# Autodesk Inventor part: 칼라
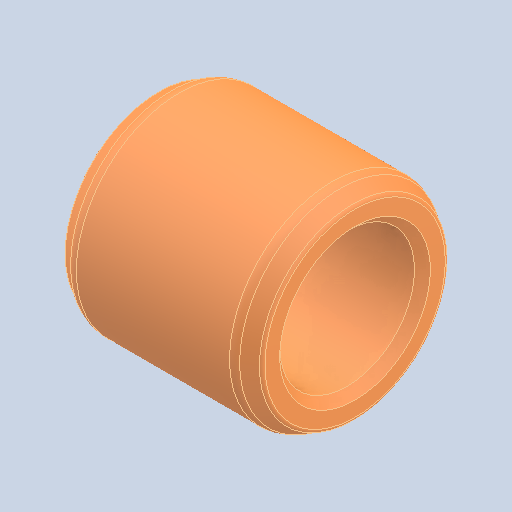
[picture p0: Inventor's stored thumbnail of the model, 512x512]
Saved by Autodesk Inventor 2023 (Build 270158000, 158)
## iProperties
Created: 2025-03
Part Number: 칼라
Material: 강철, 연강
Document SubType Name: Modeling
Designer: user
Density: 7.86 g/cm^3
Appearance: 기본값
Author: jhkim
Sending System: Autodesk Inventor 2025
Preprocessor: ST-DEVELOPER v20
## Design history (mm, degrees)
feature "솔리드1"
node "솔리드2"
